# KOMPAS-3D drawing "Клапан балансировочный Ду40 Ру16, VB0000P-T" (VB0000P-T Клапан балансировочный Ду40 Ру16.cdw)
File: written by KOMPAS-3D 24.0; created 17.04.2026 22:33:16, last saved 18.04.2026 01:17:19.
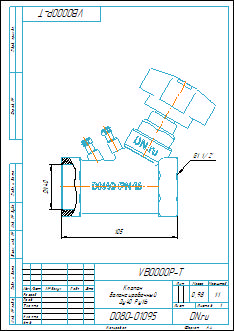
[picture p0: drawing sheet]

Document properties: Автор: tyuri; Форматы листов документа: A4; Полное имя файла: VB0000P-T Клапан балансировочный Ду40 Ру16.m3d; Масса: 0.98; Наименование: Клапан балансировочный Ду40 Ру16; Количество листов документа: 1; Примечание: D080-01095

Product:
- Body: Тело 2  | qty 1
    Масса: 1.925365
- Part/product: Клапан балансировочный Ду40 Ру16  | designation VB0000P-T
    Масса: 0.98
    Раздел спецификации: Прочие изделия
    Примечание: D080-01095

Views: Вид 1, Местный разрез 1, Справа
Referenced files in D:\Аутсорс\VB0000P-T Клапан балансировочный статический DN.ru\DN25\: VB0000P-T  Клапан балансировочный статический Ду25 Ру16.m3d
Referenced files in E:\Работа\Зайцев\АУТСОРС\Диман\Балансировка\VB0000P-T Клапан балансировочный DN.ru Ду15-50 Ру16\DN40\: VB0000P-T Клапан балансировочный Ду40 Ру16.m3d
Referenced files in D:\Аутсорс\VB0000P-T Клапан балансировочный статический DN.ru\DN20\: VB0000P-T  Клапан балансировочный статический Ду15 Ру16.cdw
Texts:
  VB0000P-T
  Клапан
  балансировочный
  Ду40 Ру16
  Клапан балансировочный Ду40 Ру16
  VB0000P-T Клапан балансировочный Ду40 Ру16
Dimensions and other numbers on the sheet: 0; 3; 2; 4; 40; 105; 1:1; 1; 0,98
